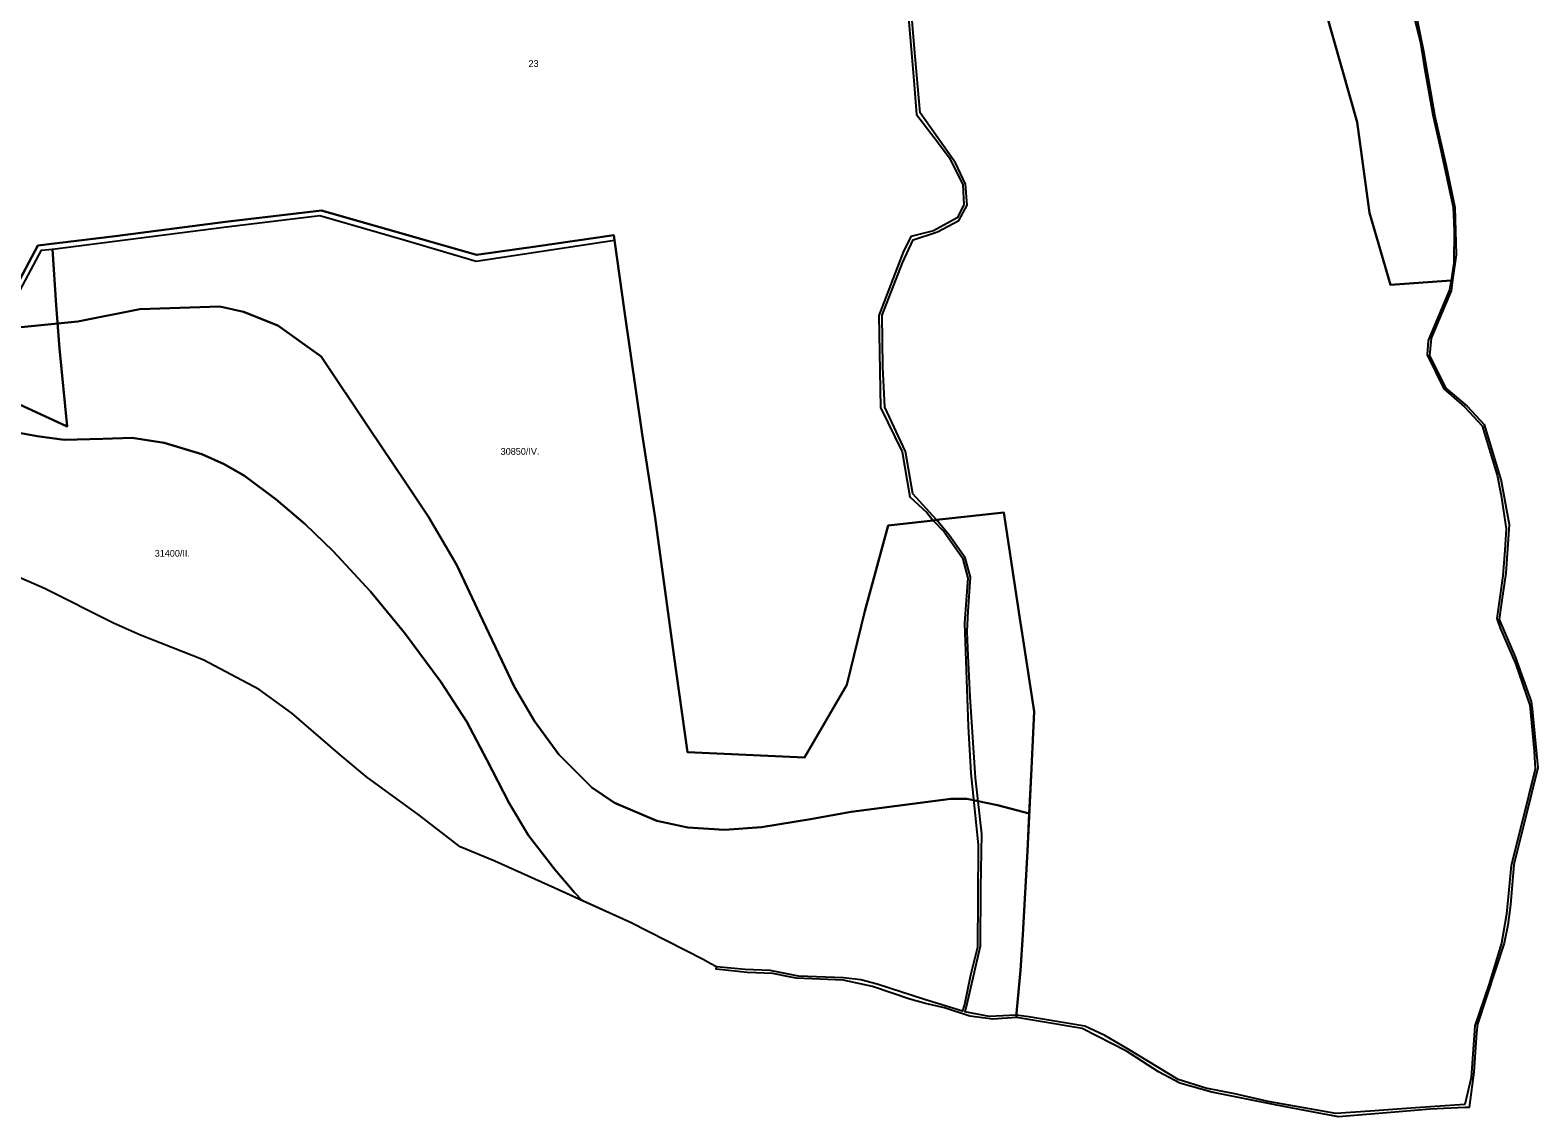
# Model space of a CAD drawing. Extents: x -532083 to -529270, y -1180561 to -1176456.
# Drawn here: x -530644 to -529531, y -1180561 to -1179759 of the extents above; entities that cross this region are included whole.
import ezdxf

# ---------------------------------------------------------------- set-up
doc = ezdxf.new("R2010")
doc.units = 0
for name, color, linetype in [('95560013', 7, 'Continuous'), ('95610013', 7, 'Continuous'), ('95620013', 7, 'Continuous'), ('95660013', 7, 'Continuous')]:
    doc.layers.add(name, color=color, linetype=linetype)

msp = doc.modelspace()

# ---------------------------------------------------------------- linework, layer by layer
at = {"layer": '95560013'}
for points in [[(-529624.9833, -1179738.56945), (-529617.3923, -1179768.42645), (-529614.7953, -1179785.45845), (-529608.4513, -1179821.46045), (-529602.3933, -1179847.48145), (-529593.3833, -1179889.57345), (-529592.6883, -1179906.81645), (-529592.9343, -1179930.68945), (-529594.9363, -1179943.75245), (-529639.6543, -1179947.08645), (-529655.1453, -1179893.84145), (-529664.1783, -1179827.02345), (-529687.4573, -1179745.53845)], [(-530652.1383, -1180035.12045), (-530616.5163, -1180051.56345), (-530622.1983, -1179994.12345), (-530624.6023, -1179962.11545), (-530627.3183, -1179920.69945), (-530498.8663, -1179904.16345), (-530429.9453, -1179895.74245), (-530367.0813, -1179914.03345), (-530314.5183, -1179929.42245), (-530212.6033, -1179914.01045), (-530205.0143, -1179966.75845), (-530192.0373, -1180057.25345), (-530182.5403, -1180119.03445), (-530168.6483, -1180220.21745), (-530158.5353, -1180291.94345), (-530072.3093, -1180296.03745), (-530041.0873, -1180242.30845), (-530027.7503, -1180188.00445), (-530010.5023, -1180124.64945), (-529977.1493, -1180121.02645), (-529969.2503, -1180129.45045), (-529955.7273, -1180148.60245), (-529951.6173, -1180163.63245), (-529952.5453, -1180176.66645), (-529954.1503, -1180196.70545), (-529952.7023, -1180238.40345), (-529951.4623, -1180273.04745), (-529949.3963, -1180307.65145), (-529944.0183, -1180360.56045), (-529944.2173, -1180400.12945), (-529944.6253, -1180435.93945), (-529949.7243, -1180456.60645), (-529954.1503, -1180478.44445), (-529955.0873, -1180481.32145), (-529955.6103, -1180483.17745), (-529971.6243, -1180478.33545), (-529983.6063, -1180474.71245), (-530018.6053, -1180463.43645), (-530030.7403, -1180460.10545), (-530043.3863, -1180458.69545), (-530076.5773, -1180457.36045), (-530097.4883, -1180453.11745), (-530116.1133, -1180452.51545), (-530137.2573, -1180450.52345), (-530141.8663, -1180447.95645), (-530147.0563, -1180445.06645), (-530200.8223, -1180417.82345), (-530256.6233, -1180392.40845), (-530300.9453, -1180372.57645), (-530326.4543, -1180362.02045), (-530356.7463, -1180338.67045), (-530395.6473, -1180310.20145), (-530415.0983, -1180293.88845), (-530450.8103, -1180263.18045), (-530474.7983, -1180245.76745), (-530516.2713, -1180223.85445), (-530562.4933, -1180205.75145), (-530582.4383, -1180196.85845), (-530633.4093, -1180171.13445), (-530680.2893, -1180150.82445)]]:
    msp.add_lwpolyline(points, dxfattribs=at)
msp.add_lwpolyline([(-529946.1073, -1180311.05245), (-529950.0443, -1180251.28245), (-529951.5463, -1180220.57545), (-529952.1093, -1180202.86745), (-529951.4373, -1180187.97145), (-529949.6733, -1180162.84445), (-529953.5543, -1180148.51245), (-529965.5483, -1180131.87945), (-529974.7203, -1180120.55445), (-529925.1553, -1180115.06945), (-529913.3373, -1180193.27945), (-529910.8683, -1180209.02745), (-529902.6953, -1180262.04745), (-529904.5833, -1180304.12645), (-529907.7113, -1180365.01045), (-529911.1793, -1180426.75845), (-529912.7673, -1180453.11945), (-529915.5293, -1180482.12345), (-529915.8003, -1180485.15545), (-529915.9223, -1180486.25045), (-529935.6973, -1180487.08845), (-529953.9393, -1180483.73545), (-529953.2433, -1180481.78045), (-529952.4073, -1180478.70645), (-529942.4373, -1180435.12345), (-529941.9763, -1180392.11445), (-529941.4603, -1180352.23045)], close=True, dxfattribs=at)
at = {"layer": '95610013'}
msp.add_lwpolyline([(-530679.7723, -1180020.73345), (-530718.0113, -1179997.29145), (-530749.8763, -1179974.91445), (-530768.2873, -1179960.35245), (-530786.3453, -1179940.81745), (-530797.3943, -1179923.83045), (-530824.8703, -1179874.67145), (-530858.8613, -1179812.72545), (-530887.7793, -1179774.78045), (-530821.6083, -1179839.30245), (-530802.5813, -1179881.01145), (-530784.2593, -1179922.01445), (-530738.3333, -1179952.54645), (-530710.5303, -1179971.53645), (-530671.4873, -1179971.33845), (-530667.1493, -1179971.14045), (-530659.6563, -1179961.84345), (-530653.1493, -1179954.52445), (-530635.5993, -1179921.49045), (-530627.3183, -1179920.69945), (-530624.6023, -1179962.11545), (-530622.1983, -1179994.12345), (-530616.5163, -1180051.56345), (-530652.1383, -1180035.12045)], close=True, dxfattribs=at)
at = {"layer": '95620013'}
for points in [[(-529687.4573, -1179745.53845), (-529664.1783, -1179827.02345), (-529655.1453, -1179893.84145), (-529639.6543, -1179947.08645), (-529594.9363, -1179943.75245), (-529596.1443, -1179950.72345), (-529611.8063, -1179988.12845), (-529612.4753, -1179998.69445), (-529600.2713, -1180023.84945), (-529585.0583, -1180037.09845), (-529572.0183, -1180051.01845), (-529560.8353, -1180087.64545), (-529557.8983, -1180102.56245), (-529554.2263, -1180127.05545), (-529555.3283, -1180142.89345), (-529556.7413, -1180161.89445), (-529561.1213, -1180193.33545), (-529558.7943, -1180200.47545), (-529547.2773, -1180226.47045), (-529536.7543, -1180257.25745), (-529533.6853, -1180291.34245), (-529532.8083, -1180304.53745), (-529542.3513, -1180343.57945), (-529550.5143, -1180375.77645), (-529554.1013, -1180411.66245), (-529557.8323, -1180432.97745), (-529567.0783, -1180463.70145), (-529577.4613, -1180494.13445), (-529580.2223, -1180532.25045), (-529584.7973, -1180552.18545), (-529621.2543, -1180554.62345), (-529654.5663, -1180557.20545), (-529680.1093, -1180558.87645), (-529729.8773, -1180549.89945), (-529754.5253, -1180544.38745), (-529775.9353, -1180539.98745), (-529796.4593, -1180533.76945), (-529833.2373, -1180511.38445), (-529850.5923, -1180501.15945), (-529865.2333, -1180494.21345), (-529906.5923, -1180487.50745), (-529915.9223, -1180486.25045), (-529915.8003, -1180485.15545), (-529915.5293, -1180482.12345), (-529912.7673, -1180453.11945), (-529911.1793, -1180426.75845), (-529907.7113, -1180365.01045), (-529904.5833, -1180304.12645), (-529902.6953, -1180262.04745), (-529910.8683, -1180209.02745), (-529913.3373, -1180193.27945), (-529925.1553, -1180115.06945), (-529974.7203, -1180120.55445), (-529992.3073, -1180101.42345), (-529997.7933, -1180070.07445), (-530013.0613, -1180037.28945), (-530014.4073, -1180007.54645), (-530014.9323, -1179969.29745), (-529999.8473, -1179930.78745), (-529992.1313, -1179913.72845), (-529973.9833, -1179907.85145), (-529958.2653, -1179899.53745), (-529952.2643, -1179888.07045), (-529953.3483, -1179872.56745), (-529960.9023, -1179856.89545), (-529969.6583, -1179844.49445), (-529986.8263, -1179820.03945), (-529990.5303, -1179778.41345), (-529994.4923, -1179731.13945)], [(-529996.1163, -1179741.22645), (-529991.5243, -1179796.11745), (-529989.6863, -1179821.18845), (-529976.5293, -1179838.31545), (-529965.3083, -1179853.32445), (-529955.3343, -1179873.08545), (-529954.7513, -1179887.91745), (-529959.4653, -1179897.51445), (-529976.9363, -1179907.11245), (-529993.7133, -1179911.42345), (-529999.3973, -1179922.82945), (-530017.4143, -1179969.54845), (-530016.0943, -1180037.55045), (-530000.0933, -1180070.30645), (-529994.5693, -1180103.55145), (-529982.0353, -1180115.05945), (-529977.1493, -1180121.02645), (-530010.5023, -1180124.64945), (-530027.7503, -1180188.00445), (-530041.0873, -1180242.30845), (-530072.3093, -1180296.03745), (-530158.5353, -1180291.94345), (-530168.6483, -1180220.21745), (-530182.5403, -1180119.03445), (-530192.0373, -1180057.25345), (-530205.0143, -1179966.75845), (-530212.6033, -1179914.01045), (-530213.0623, -1179910.37245), (-530270.4793, -1179918.60045), (-530314.3973, -1179924.94345), (-530357.5583, -1179912.56445), (-530428.7603, -1179892.11645), (-530499.6223, -1179900.56645), (-530581.2093, -1179911.06445), (-530638.1853, -1179917.86845), (-530656.2083, -1179951.88945)]]:
    msp.add_lwpolyline(points, dxfattribs=at)
at = {"layer": '95660013'}
for points in [[(-529687.4573, -1179745.53845), (-529664.1783, -1179827.02345), (-529655.1453, -1179893.84145), (-529639.6543, -1179947.08645), (-529594.9363, -1179943.75245), (-529593.7803, -1179943.66645), (-529594.8263, -1179951.36445), (-529599.7513, -1179963.03445), (-529609.7043, -1179986.32845), (-529610.7653, -1179999.24045), (-529598.9323, -1180023.30345), (-529582.9963, -1180036.56345), (-529570.5013, -1180050.18745), (-529558.0573, -1180091.81745), (-529552.1033, -1180124.02445), (-529554.4423, -1180159.85745), (-529557.4193, -1180179.90645), (-529559.3433, -1180194.16845), (-529547.5773, -1180221.76545), (-529535.8103, -1180254.74245), (-529535.0893, -1180260.11145), (-529530.8873, -1180303.59345), (-529540.1513, -1180341.45445), (-529548.7033, -1180374.92745), (-529551.0503, -1180404.86745), (-529553.0633, -1180419.83745), (-529555.8713, -1180433.00145), (-529575.5323, -1180492.87245), (-529576.2223, -1180499.17045), (-529578.0823, -1180528.26345), (-529581.3663, -1180552.30645), (-529581.6293, -1180554.42945), (-529584.6303, -1180554.39145), (-529610.3833, -1180555.73045), (-529633.4643, -1180557.64445), (-529678.1023, -1180561.28045), (-529697.7713, -1180557.46945), (-529723.4733, -1180552.59845), (-529771.4523, -1180543.00145), (-529795.1553, -1180536.41245), (-529810.8833, -1180528.12745), (-529834.4333, -1180512.74345), (-529867.1573, -1180496.12445), (-529898.1013, -1180490.90445), (-529915.8543, -1180487.95345), (-529915.8003, -1180485.15545), (-529915.5293, -1180482.12345), (-529912.7673, -1180453.11945), (-529911.1793, -1180426.75845), (-529907.7113, -1180365.01045), (-529906.2933, -1180337.41445), (-529904.5833, -1180304.12645), (-529902.6953, -1180262.04745), (-529910.8683, -1180209.02745), (-529913.3373, -1180193.27945), (-529925.1553, -1180115.06945), (-529974.7203, -1180120.55445), (-529977.1493, -1180121.02645), (-530010.5023, -1180124.64945), (-530027.7503, -1180188.00445), (-530041.0873, -1180242.30845), (-530072.3093, -1180296.03745), (-530158.5353, -1180291.94345), (-530168.6483, -1180220.21745), (-530182.5403, -1180119.03445), (-530192.0373, -1180057.25345), (-530205.0143, -1179966.75845), (-530212.6033, -1179914.01045), (-530213.0623, -1179910.37245), (-530270.4793, -1179918.60045), (-530314.3973, -1179924.94345), (-530357.5583, -1179912.56445), (-530428.7603, -1179892.11645), (-530499.6223, -1179900.56645), (-530581.2093, -1179911.06445), (-530638.1853, -1179917.86845), (-530656.2083, -1179951.88945)], [(-529620.5403, -1179749.25945), (-529615.2783, -1179774.41745), (-529606.8593, -1179822.60145), (-529598.6743, -1179859.02145), (-529592.2033, -1179889.92345), (-529591.2253, -1179924.87345), (-529593.7803, -1179943.66645), (-529594.9363, -1179943.75245), (-529639.6543, -1179947.08645), (-529655.1453, -1179893.84145), (-529664.1783, -1179827.02345), (-529687.4573, -1179745.53845)], [(-530656.2083, -1179951.88945), (-530638.1853, -1179917.86845), (-530581.2093, -1179911.06445), (-530499.6223, -1179900.56645), (-530428.7603, -1179892.11645), (-530357.5583, -1179912.56445), (-530314.3973, -1179924.94345), (-530270.4793, -1179918.60045), (-530213.0623, -1179910.37245), (-530212.6033, -1179914.01045), (-530205.0143, -1179966.75845), (-530192.0373, -1180057.25345), (-530182.5403, -1180119.03445), (-530168.6483, -1180220.21745), (-530158.5353, -1180291.94345), (-530072.3093, -1180296.03745), (-530041.0873, -1180242.30845), (-530027.7503, -1180188.00445), (-530010.5023, -1180124.64945), (-529977.1493, -1180121.02645), (-529974.7203, -1180120.55445), (-529925.1553, -1180115.06945), (-529913.3373, -1180193.27945), (-529910.8683, -1180209.02745), (-529902.6953, -1180262.04745), (-529904.5833, -1180304.12645), (-529906.2933, -1180337.41445), (-529929.7753, -1180331.06545), (-529952.3033, -1180326.44145), (-529964.2653, -1180326.53245), (-529998.1053, -1180330.83545), (-530037.6843, -1180336.00045), (-530067.8733, -1180341.57645), (-530103.9513, -1180347.45345), (-530131.2813, -1180349.46545), (-530158.4563, -1180347.63845), (-530181.2693, -1180342.67045), (-530212.4953, -1180329.48945), (-530229.3083, -1180318.21545), (-530253.5443, -1180293.87045), (-530271.6223, -1180269.09845), (-530286.6223, -1180243.53645), (-530312.0133, -1180190.08545), (-530328.9753, -1180154.06445), (-530349.7813, -1180118.26945), (-530366.5603, -1180093.26045), (-530393.8033, -1180052.65545), (-530429.1303, -1180000.00045), (-530461.1253, -1179977.00045), (-530486.5003, -1179967.00045), (-530503.8123, -1179963.00045), (-530562.8123, -1179965.00045), (-530608.6873, -1179974.00045), (-530657.8753, -1179979.00045)], [(-530657.8753, -1179979.00045), (-530608.6873, -1179974.00045), (-530562.8123, -1179965.00045), (-530503.8123, -1179963.00045), (-530486.5003, -1179967.00045), (-530461.1253, -1179977.00045), (-530429.1303, -1180000.00045), (-530393.8033, -1180052.65545), (-530366.5603, -1180093.26045), (-530349.7813, -1180118.26945), (-530328.9753, -1180154.06445), (-530312.0133, -1180190.08545), (-530286.6223, -1180243.53645), (-530271.6223, -1180269.09845), (-530253.5443, -1180293.87045), (-530229.3083, -1180318.21545), (-530212.4953, -1180329.48945), (-530181.2693, -1180342.67045), (-530158.4563, -1180347.63845), (-530131.2813, -1180349.46545), (-530103.9513, -1180347.45345), (-530067.8733, -1180341.57645), (-530037.6843, -1180336.00045), (-529998.1053, -1180330.83545), (-529964.2653, -1180326.53245), (-529952.3033, -1180326.44145), (-529929.7753, -1180331.06545), (-529906.2933, -1180337.41445), (-529907.7113, -1180365.01045), (-529911.1793, -1180426.75845), (-529912.7673, -1180453.11945), (-529915.5293, -1180482.12345), (-529915.8003, -1180485.15545), (-529915.8543, -1180487.95345), (-529933.3033, -1180489.07045), (-529950.2583, -1180486.90045), (-529968.9873, -1180480.86145), (-529983.0333, -1180477.67345), (-529994.5723, -1180474.31845), (-530021.9963, -1180465.09245), (-530043.7343, -1180460.39545), (-530078.3493, -1180458.88645), (-530083.4813, -1180457.89445), (-530095.6203, -1180455.54445), (-530114.5753, -1180454.79645), (-530137.3633, -1180452.12545), (-530137.2573, -1180450.52345), (-530141.8663, -1180447.95645), (-530147.0563, -1180445.06645), (-530200.8223, -1180417.82345), (-530236.1013, -1180401.75545), (-530242.2523, -1180395.34745), (-530256.6203, -1180378.67645), (-530275.9623, -1180353.43845), (-530290.2253, -1180329.71745), (-530306.6633, -1180297.71545), (-530321.4723, -1180269.60945), (-530340.6353, -1180240.13345), (-530367.5303, -1180204.02845), (-530392.6213, -1180173.44445), (-530420.3093, -1180143.53645), (-530440.9783, -1180123.75545), (-530462.1993, -1180105.50445), (-530485.7113, -1180087.96545), (-530500.6753, -1180079.39845), (-530517.1203, -1180072.07645), (-530544.8823, -1180063.67245), (-530568.6853, -1180060.07745), (-530590.2253, -1180060.61345), (-530618.7983, -1180061.53745), (-530638.7893, -1180058.83745), (-530664.1823, -1180054.08145)], [(-530664.1823, -1180054.08145), (-530638.7893, -1180058.83745), (-530618.7983, -1180061.53745), (-530590.2253, -1180060.61345), (-530568.6853, -1180060.07745), (-530544.8823, -1180063.67245), (-530517.1203, -1180072.07645), (-530500.6753, -1180079.39845), (-530485.7113, -1180087.96545), (-530462.1993, -1180105.50445), (-530440.9783, -1180123.75545), (-530420.3093, -1180143.53645), (-530392.6213, -1180173.44445), (-530367.5303, -1180204.02845), (-530340.6353, -1180240.13345), (-530321.4723, -1180269.60945), (-530306.6633, -1180297.71545), (-530290.2253, -1180329.71745), (-530275.9623, -1180353.43845), (-530256.6203, -1180378.67645), (-530242.2523, -1180395.34745), (-530236.1013, -1180401.75545), (-530256.6233, -1180392.40845), (-530300.9453, -1180372.57645), (-530326.4543, -1180362.02045), (-530356.7463, -1180338.67045), (-530395.6473, -1180310.20145), (-530415.0983, -1180293.88845), (-530450.8103, -1180263.18045), (-530474.7983, -1180245.76745), (-530516.2713, -1180223.85445), (-530562.4933, -1180205.75145), (-530582.4383, -1180196.85845), (-530633.4093, -1180171.13445), (-530680.2893, -1180150.82445)]]:
    msp.add_lwpolyline(points, dxfattribs=at)

# ---------------------------------------------------------------- texts
for s, rotation, p in [('23', 0.00000001, (-530276.00034, -1179786.12995)), ('30850/IV.', 359.99999995, (-530296.5693, -1180072.48272)), ('31400/II.', 0, (-530551.92882, -1180147.71195))]:
    msp.add_text(s, height=5, rotation=rotation, dxfattribs=at).set_placement(p)

doc.saveas('drawing.dxf')
